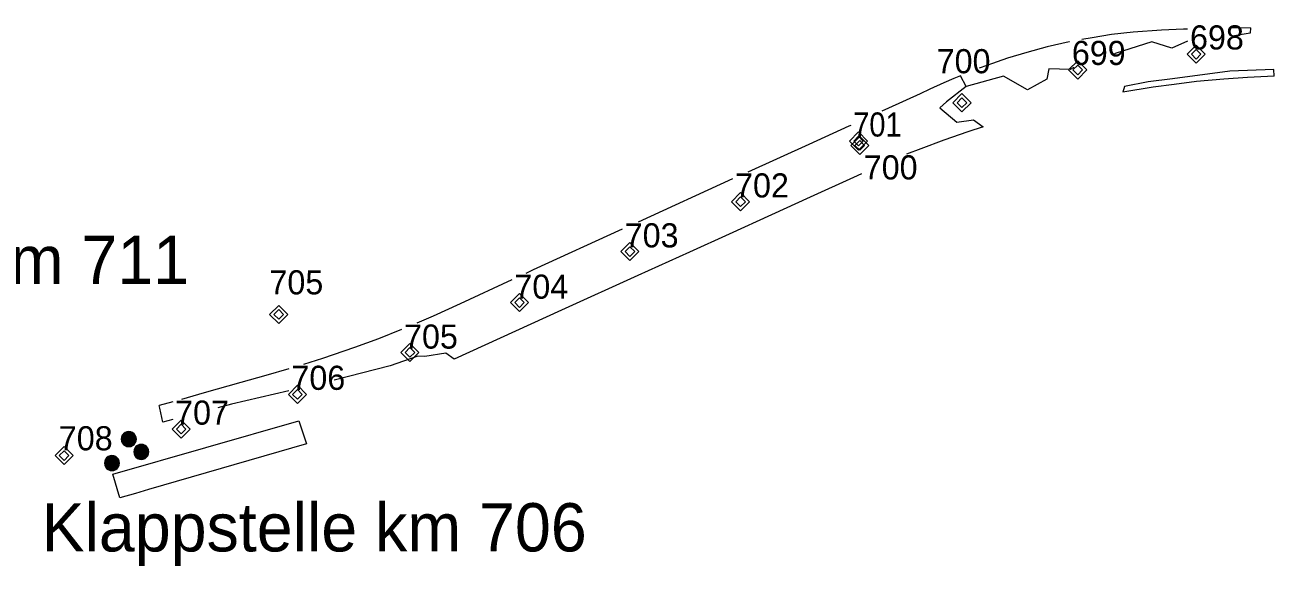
# Model space of a CAD drawing. Extents: x 3461750 to 3585707, y 5917729 to 5985917.
# Drawn here: x 3498273 to 3508628, y 5967849 to 5972332 of the extents above; entities that cross this region are included whole.
import ezdxf

# ---------------------------------------------------------------- set-up
doc = ezdxf.new("R2010")
doc.units = 0
doc.header["$LTSCALE"] = 80
doc.layers.add('11', color=7, linetype='Continuous')
for name, color, linetype, lineweight in [('12', 7, 'Continuous', 13), ('13', 7, 'Continuous', 13), ('14', 7, 'Continuous', 13), ('15', 7, 'Continuous', 13), ('2', 7, 'Continuous', 13), ('3', 7, 'Continuous', 13), ('6', 7, 'Continuous', 13)]:
    doc.layers.add(name, color=color, linetype=linetype, lineweight=lineweight)

msp = doc.modelspace()

# ---------------------------------------------------------------- hatches: boundary and pattern name
at = {"layer": '3'}
for points in [[(3499197.26, 5968900.74), (3499194.33, 5968917.37), (3499188.08, 5968932.46), (3499178.13, 5968945.42), (3499165.17, 5968955.36), (3499150.08, 5968961.61), (3499133.89, 5968963.75), (3499117.69, 5968961.61), (3499102.6, 5968955.36), (3499089.64, 5968945.42), (3499079.7, 5968932.46), (3499073.44, 5968917.37), (3499071.31, 5968901.17), (3499073.44, 5968884.98), (3499079.7, 5968869.88), (3499089.64, 5968856.92), (3499102.6, 5968846.98), (3499117.69, 5968840.73), (3499133.89, 5968838.6), (3499150.08, 5968840.73), (3499165.17, 5968846.98), (3499178.13, 5968856.92), (3499188.08, 5968869.88), (3499194.33, 5968884.98)], [(3499300.97, 5968794.3), (3499298.04, 5968810.92), (3499291.79, 5968826.01), (3499281.85, 5968838.97), (3499268.89, 5968848.92), (3499253.79, 5968855.17), (3499237.6, 5968857.3), (3499221.4, 5968855.17), (3499206.31, 5968848.92), (3499193.35, 5968838.97), (3499183.41, 5968826.01), (3499177.16, 5968810.92), (3499175.02, 5968794.73), (3499177.16, 5968778.53), (3499183.41, 5968763.44), (3499193.35, 5968750.48), (3499206.31, 5968740.54), (3499221.4, 5968734.28), (3499237.6, 5968732.15), (3499253.79, 5968734.28), (3499268.89, 5968740.54), (3499281.85, 5968750.48), (3499291.79, 5968763.44), (3499298.04, 5968778.53)], [(3499058.05, 5968701.62), (3499055.12, 5968718.25), (3499048.87, 5968733.34), (3499038.93, 5968746.3), (3499025.97, 5968756.24), (3499010.87, 5968762.49), (3498994.68, 5968764.63), (3498978.48, 5968762.49), (3498963.39, 5968756.24), (3498950.43, 5968746.3), (3498940.49, 5968733.34), (3498934.24, 5968718.25), (3498932.1, 5968702.05), (3498934.24, 5968685.86), (3498940.49, 5968670.76), (3498950.43, 5968657.8), (3498963.39, 5968647.86), (3498978.48, 5968641.61), (3498994.68, 5968639.48), (3499010.87, 5968641.61), (3499025.97, 5968647.86), (3499038.93, 5968657.8), (3499048.87, 5968670.76), (3499055.12, 5968685.86)]]:
    msp.add_hatch(color=256, dxfattribs=at).paths.add_polyline_path(points)

# ---------------------------------------------------------------- linework, layer by layer
at = {"layer": '12'}
for points in [[(3500376.79, 5970008.99), (3500301.7, 5969933.9), (3500376.79, 5969858.81), (3500451.88, 5969933.9)], [(3500376.79, 5969973.59), (3500337.1, 5969933.9), (3500376.79, 5969894.21), (3500416.48, 5969933.9)]]:
    msp.add_lwpolyline(points, close=True, dxfattribs=at)
at = {"layer": '13'}
for points in [[(3505193.73, 5971409.48), (3505118.64, 5971334.39), (3505193.73, 5971259.3), (3505268.82, 5971334.39)], [(3505193.73, 5971374.08), (3505154.04, 5971334.39), (3505193.73, 5971294.69), (3505233.43, 5971334.39)]]:
    msp.add_lwpolyline(points, close=True, dxfattribs=at)
at = {"layer": '14'}
for points in [[(3506040.9, 5971763.58), (3505965.81, 5971688.49), (3506040.9, 5971613.4), (3506115.99, 5971688.49)], [(3506040.9, 5971728.18), (3506001.21, 5971688.49), (3506040.9, 5971648.8), (3506080.59, 5971688.49)]]:
    msp.add_lwpolyline(points, close=True, dxfattribs=at)
at = {"layer": '15'}
for points in [[(3507982.6, 5972165.04), (3507907.51, 5972089.95), (3507982.6, 5972014.86), (3508057.69, 5972089.95)], [(3507982.6, 5972129.65), (3507942.91, 5972089.95), (3507982.6, 5972050.26), (3508022.29, 5972089.95)], [(3507000.72, 5972034.87), (3506925.63, 5971959.78), (3507000.72, 5971884.69), (3507075.81, 5971959.78)], [(3507000.72, 5971999.47), (3506961.02, 5971959.78), (3507000.72, 5971920.09), (3507040.41, 5971959.78)], [(3505183.63, 5971445.71), (3505108.54, 5971370.62), (3505183.63, 5971295.53), (3505258.72, 5971370.62)], [(3505183.63, 5971410.31), (3505143.93, 5971370.62), (3505183.63, 5971330.93), (3505223.32, 5971370.62)], [(3504205.5, 5970943.17), (3504130.41, 5970868.08), (3504205.5, 5970792.99), (3504280.59, 5970868.08)], [(3504205.5, 5970907.77), (3504165.81, 5970868.08), (3504205.5, 5970828.39), (3504245.19, 5970868.08)], [(3503288.41, 5970529.99), (3503213.32, 5970454.9), (3503288.41, 5970379.8), (3503363.5, 5970454.9)], [(3503288.41, 5970494.59), (3503248.72, 5970454.9), (3503288.41, 5970415.2), (3503328.1, 5970454.9)], [(3502373.28, 5970107.04), (3502298.18, 5970031.95), (3502373.28, 5969956.86), (3502448.37, 5970031.95)], [(3502373.28, 5970071.64), (3502333.58, 5970031.95), (3502373.28, 5969992.25), (3502412.97, 5970031.95)], [(3501464.49, 5969694.44), (3501389.4, 5969619.35), (3501464.49, 5969544.26), (3501539.58, 5969619.35)], [(3501464.49, 5969659.04), (3501424.79, 5969619.35), (3501464.49, 5969579.66), (3501504.18, 5969619.35)], [(3500531.87, 5969346.59), (3500456.78, 5969271.5), (3500531.87, 5969196.41), (3500606.96, 5969271.5)], [(3500531.87, 5969311.19), (3500492.18, 5969271.5), (3500531.87, 5969231.8), (3500571.56, 5969271.5)], [(3499568.49, 5969058.79), (3499493.4, 5968983.7), (3499568.49, 5968908.61), (3499643.58, 5968983.7)], [(3499568.49, 5969023.4), (3499528.8, 5968983.7), (3499568.49, 5968944.01), (3499608.18, 5968983.7)], [(3498597.59, 5968839.56), (3498522.5, 5968764.47), (3498597.59, 5968689.38), (3498672.68, 5968764.47)], [(3498597.59, 5968804.16), (3498557.9, 5968764.47), (3498597.59, 5968724.77), (3498637.28, 5968764.47)]]:
    msp.add_lwpolyline(points, close=True, dxfattribs=at)
at = {"layer": '2'}
for p, q in [((3508434.18, 5972308.11), (3508285.2, 5972304.95)), ((3506029.52, 5971912.2), (3506029.05, 5971912.01)), ((3506076.17, 5971822.27), (3506029.05, 5971912.01)), ((3505700.68, 5971306.84), (3505580.5, 5971261.11)), ((3504140, 5971056.34), (3503357.6, 5970699.3)), ((3499498.1, 5969210.58), (3499384.52, 5969180.08)), ((3499391.31, 5969156.84), (3499384.52, 5969180.08))]:
    msp.add_line(p, q, dxfattribs=at)
for points in [[(3507911.6, 5972297.03), (3507876.66, 5972296.29), (3507695.21, 5972290.43), (3507460.69, 5972272.95), (3507281.93, 5972252.64), (3507119.24, 5972226.07), (3507034.38, 5972210.8)], [(3508434.18, 5972308.11), (3508431.1, 5972265.62), (3508285.2, 5972239.16)], [(3506932.1, 5972192.39), (3506929.35, 5972191.89), (3506746.92, 5972150.68), (3506578.32, 5972104.79), (3506417.82, 5972056.05), (3506245.9, 5971997.46), (3506184.9, 5971973.83)], [(3507911.6, 5972198.7), (3507779.93, 5972139.45), (3507615.77, 5972191.7), (3507310.01, 5972095.61), (3507305.7, 5972094.49)], [(3506967.35, 5971980.8), (3506938.92, 5971964.55), (3506760.74, 5971968.95), (3506745.41, 5971883.01), (3506583.94, 5971796), (3506385.01, 5971907.23), (3506076.17, 5971822.27)], [(3508628.03, 5971909.08), (3508627.59, 5971963.09), (3508262.21, 5971949.71), (3507787.6, 5971886.91), (3507584.03, 5971860.35), (3507387.65, 5971823.63), (3507374.41, 5971775.2)], [(3506029.05, 5971912.01), (3505973.93, 5971889.65), (3505890.14, 5971851.95), (3505773.63, 5971800.29), (3505693.9, 5971762.6)], [(3508628.03, 5971909.08), (3508409.08, 5971898.05), (3508212.21, 5971884.57), (3507986.47, 5971864.06), (3507799.07, 5971840.04), (3507625.93, 5971816.31), (3507374.41, 5971775.2)], [(3505693.9, 5971762.6), (3505430.81, 5971641.99), (3505377.54, 5971617.8)], [(3506076.17, 5971822.27), (3505912.89, 5971694.43), (3505858.64, 5971646.78), (3505999.66, 5971527.44), (3506137.11, 5971545.12), (3506216.41, 5971487.79)], [(3505119.2, 5971500.47), (3505104.2, 5971493.65), (3504772.17, 5971342.58), (3504264.97, 5971113)], [(3506216.41, 5971487.79), (3506090.58, 5971447.17), (3505889.89, 5971377.93), (3505700.68, 5971306.84)], [(3505206.9, 5971098.88), (3505140.72, 5971068.95), (3504781.59, 5970906.45), (3504461.47, 5970760.16), (3504110.74, 5970599.61), (3503782.28, 5970450.29), (3503352.78, 5970255.96), (3502722.07, 5969969.43), (3502086.08, 5969679.88), (3501830.91, 5969563.77)], [(3503225.3, 5970639.07), (3502485.45, 5970302.25), (3502424.95, 5970274.2)], [(3502310.5, 5970221.13), (3501882.28, 5970022.56), (3501656.25, 5969919.53), (3501521.04, 5969860.5)], [(3501395.8, 5969807.88), (3501205.32, 5969732.71), (3501006.3, 5969661.13), (3500740.38, 5969567.97), (3500582.94, 5969518.9)], [(3501529.25, 5969588.09), (3501300.24, 5969507.71), (3500835.7, 5969389.09)], [(3501830.91, 5969563.77), (3501761.57, 5969612.7), (3501587.99, 5969586.33), (3501529.25, 5969588.09)], [(3500462.1, 5969482.47), (3500270.51, 5969428.71), (3500062.5, 5969368.95), (3499758.45, 5969283.11), (3499569.94, 5969230.4)], [(3500462.1, 5969299.57), (3499986.23, 5969191.31), (3499871.7, 5969161.34)], [(3499498.1, 5969063.57), (3499417.14, 5969042.38), (3499391.31, 5969156.84)]]:
    msp.add_lwpolyline(points, dxfattribs=at)
at = {"layer": '3'}
for points in [[(3499197.26, 5968900.74), (3499194.33, 5968917.37), (3499188.08, 5968932.46), (3499178.13, 5968945.42), (3499165.17, 5968955.36), (3499150.08, 5968961.61), (3499133.89, 5968963.75), (3499117.69, 5968961.61), (3499102.6, 5968955.36), (3499089.64, 5968945.42), (3499079.7, 5968932.46), (3499073.44, 5968917.37), (3499071.31, 5968901.17), (3499073.44, 5968884.98), (3499079.7, 5968869.88), (3499089.64, 5968856.92), (3499102.6, 5968846.98), (3499117.69, 5968840.73), (3499133.89, 5968838.6), (3499150.08, 5968840.73), (3499165.17, 5968846.98), (3499178.13, 5968856.92), (3499188.08, 5968869.88), (3499194.33, 5968884.98)], [(3499300.97, 5968794.3), (3499298.04, 5968810.92), (3499291.79, 5968826.01), (3499281.85, 5968838.97), (3499268.89, 5968848.92), (3499253.79, 5968855.17), (3499237.6, 5968857.3), (3499221.4, 5968855.17), (3499206.31, 5968848.92), (3499193.35, 5968838.97), (3499183.41, 5968826.01), (3499177.16, 5968810.92), (3499175.02, 5968794.73), (3499177.16, 5968778.53), (3499183.41, 5968763.44), (3499193.35, 5968750.48), (3499206.31, 5968740.54), (3499221.4, 5968734.28), (3499237.6, 5968732.15), (3499253.79, 5968734.28), (3499268.89, 5968740.54), (3499281.85, 5968750.48), (3499291.79, 5968763.44), (3499298.04, 5968778.53)], [(3499058.05, 5968701.62), (3499055.12, 5968718.25), (3499048.87, 5968733.34), (3499038.93, 5968746.3), (3499025.97, 5968756.24), (3499010.87, 5968762.49), (3498994.68, 5968764.63), (3498978.48, 5968762.49), (3498963.39, 5968756.24), (3498950.43, 5968746.3), (3498940.49, 5968733.34), (3498934.24, 5968718.25), (3498932.1, 5968702.05), (3498934.24, 5968685.86), (3498940.49, 5968670.76), (3498950.43, 5968657.8), (3498963.39, 5968647.86), (3498978.48, 5968641.61), (3498994.68, 5968639.48), (3499010.87, 5968641.61), (3499025.97, 5968647.86), (3499038.93, 5968657.8), (3499048.87, 5968670.76), (3499055.12, 5968685.86)]]:
    msp.add_lwpolyline(points, close=True, dxfattribs=at)
at = {"layer": '6'}
msp.add_lwpolyline([(3499060.4, 5968414.75), (3499002.88, 5968611.13), (3500543.85, 5969051.66), (3500607.32, 5968860.55), (3499298.29, 5968482.91), (3499189.79, 5968450.59)], close=True, dxfattribs=at)

# ---------------------------------------------------------------- texts
at = {"layer": '11'}
for s, p in [('Klappstelle km 711 ', (3495114.5, 5970186)), ('Klappstelle km 706 ', (3498410.8, 5967970.1))]:
    msp.add_text(s, height=400, dxfattribs=at).set_placement(p)
at = {"layer": '12'}
msp.add_text('705', height=200, dxfattribs=at).set_placement((3500300, 5970100))
at = {"layer": '13'}
msp.add_text('700', height=200, dxfattribs=at).set_placement((3505226.9, 5971052.4))
at = {"layer": '14'}
msp.add_text('700', height=200, dxfattribs=at).set_placement((3505831.3, 5971932.2))
at = {"layer": '15'}
for s, p in [('698', (3507931.6, 5972129.2)), ('699', (3506952.1, 5972000.8)), ('702', (3504160, 5970903)), ('703', (3503245.3, 5970489.3)), ('704', (3502330.5, 5970064.2)), ('705', (3501415.8, 5969650.5)), ('706', (3500482.1, 5969308.9)), ('707', (3499518.1, 5969020.4)), ('708', (3498554, 5968807.9))]:
    msp.add_text(s, height=200, dxfattribs=at).set_placement(p)
at = {"layer": '15', "width": 0.9}
msp.add_text('701', height=200, dxfattribs=at).set_placement((3505139.2, 5971407.8))

doc.saveas('drawing.dxf')
